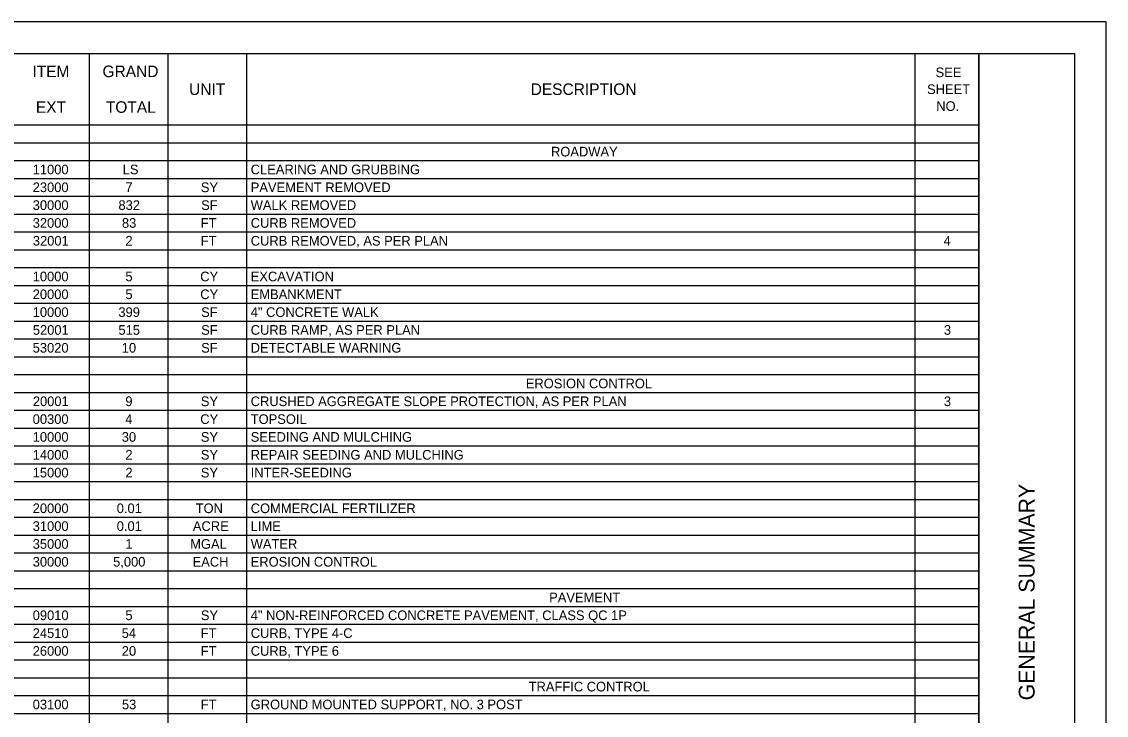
# Model space of a CAD drawing. Extents: x 0 to 34, y 0 to 22.
# Drawn here: x 16.98 to 34, y 11.11 to 22 of the extents above; entities that cross this region are included whole.
import ezdxf

# ---------------------------------------------------------------- set-up
doc = ezdxf.new("R2010")
doc.units = 0
for name, color, linetype in [('SH_Border', 7, 'Continuous'), ('SH_Cut_Line', 7, 'Continuous'), ('SH_Data', 7, 'Continuous'), ('SH_Text', 7, 'Continuous')]:
    doc.layers.add(name, color=color, linetype=linetype)

msp = doc.modelspace()

# ---------------------------------------------------------------- linework, layer by layer
at = {"layer": 'SH_Border'}
msp.add_line((32, 0.5), (32, 21.5), dxfattribs=at)
msp.add_lwpolyline([(1.5, 21.5), (33.5, 21.5), (33.5, 0.5), (1.5, 0.5)], close=True, dxfattribs=at)
at = {"layer": 'SH_Cut_Line'}
msp.add_lwpolyline([(0, 0), (34, 0), (34, 22), (0, 22)], close=True, dxfattribs=at)
at = {"layer": 'SH_Text'}
for p, q in [((1.5, 21.5), (32, 21.5)), ((18.035, 21.5), (18.035, 0.5)), ((19.27, 21.5), (19.27, 0.5)), ((20.505, 21.5), (20.505, 0.5)), ((30.995, 21.5), (30.995, 0.5)), ((32, 21.5), (32, 0.5)), ((1.5, 20.38), (32, 20.38)), ((1.5, 20.1), (32, 20.1)), ((1.5, 19.82), (32, 19.82)), ((1.5, 19.54), (32, 19.54)), ((1.5, 19.26), (32, 19.26)), ((1.5, 18.98), (32, 18.98)), ((1.5, 18.7), (32, 18.7)), ((1.5, 18.42), (32, 18.42)), ((1.5, 18.14), (32, 18.14)), ((1.5, 17.86), (32, 17.86)), ((1.5, 17.58), (32, 17.58)), ((1.5, 17.3), (32, 17.3)), ((1.5, 17.02), (32, 17.02)), ((1.5, 16.74), (32, 16.74)), ((1.5, 16.46), (32, 16.46)), ((1.5, 16.18), (32, 16.18)), ((1.5, 15.9), (32, 15.9)), ((1.5, 15.62), (32, 15.62)), ((1.5, 15.34), (32, 15.34)), ((1.5, 15.06), (32, 15.06)), ((1.5, 14.78), (32, 14.78)), ((1.5, 14.5), (32, 14.5)), ((1.5, 14.22), (32, 14.22)), ((1.5, 13.94), (32, 13.94)), ((1.5, 13.66), (32, 13.66)), ((1.5, 13.38), (32, 13.38)), ((1.5, 13.1), (32, 13.1)), ((1.5, 12.82), (32, 12.82)), ((1.5, 12.54), (32, 12.54)), ((1.5, 12.26), (32, 12.26)), ((1.5, 11.98), (32, 11.98)), ((1.5, 11.7), (32, 11.7)), ((1.5, 11.42), (32, 11.42)), ((1.5, 11.14), (32, 11.14))]:
    msp.add_line(p, q, dxfattribs=at)

# ---------------------------------------------------------------- texts
at = {"layer": 'SH_Data'}
msp.add_text('GENERAL SUMMARY', height=0.25, rotation=90, dxfattribs=at).set_placement((32.875, 11.344))
at = {"layer": 'SH_Text'}
for s, height, p in [('ITEM', 0.1818, (17.145, 21.129)), ('GRAND', 0.1818, (18.245, 21.129)), ('SEE ', 0.1515, (31.32, 21.129)), ('UNIT', 0.1818, (19.604, 20.849)), ('DESCRIPTION', 0.18184, (24.965, 20.849)), ('SHEET ', 0.1515, (31.187, 20.864)), ('EXT', 0.1818, (17.199, 20.569)), ('TOTAL', 0.1818, (18.297, 20.569)), ('NO.', 0.1515, (31.331, 20.599)), ('ROADWAY', 0.1515, (25.284, 19.884)), ('11000', 0.1515, (17.149, 19.604)), ('LS', 0.1515, (18.562, 19.604)), ('CLEARING AND GRUBBING', 0.15153, (20.571, 19.604)), ('23000', 0.1515, (17.149, 19.324)), ('7', 0.152, (18.603, 19.324)), ('SY', 0.1515, (19.788, 19.324)), ('PAVEMENT REMOVED', 0.15153, (20.571, 19.324)), ('30000', 0.1515, (17.149, 19.044)), ('832', 0.1515, (18.495, 19.044)), ('SF', 0.1515, (19.793, 19.044)), ('WALK REMOVED', 0.15153, (20.571, 19.044)), ('32000', 0.1515, (17.149, 18.764)), ('83', 0.1515, (18.55, 18.764)), ('FT', 0.1515, (19.786, 18.764)), ('CURB REMOVED', 0.15153, (20.571, 18.764)), ('32001', 0.1515, (17.151, 18.484)), ('2', 0.152, (18.604, 18.484)), ('FT', 0.1515, (19.786, 18.484)), ('CURB REMOVED, AS PER PLAN', 0.15153, (20.571, 18.484)), ('4', 0.152, (31.446, 18.484)), ('10000', 0.1515, (17.149, 17.924)), ('5', 0.152, (18.604, 17.924)), ('CY', 0.1515, (19.779, 17.924)), ('EXCAVATION', 0.1515, (20.571, 17.924)), ('20000', 0.1515, (17.149, 17.644)), ('5', 0.152, (18.604, 17.644)), ('CY', 0.1515, (19.779, 17.644)), ('EMBANKMENT', 0.1515, (20.571, 17.644)), ('10000', 0.1515, (17.149, 17.364)), ('399', 0.1515, (18.494, 17.364)), ('SF', 0.1515, (19.793, 17.364)), ('4" CONCRETE WALK', 0.15153, (20.571, 17.364)), ('52001', 0.1515, (17.151, 17.084)), ('515', 0.1515, (18.495, 17.084)), ('SF', 0.1515, (19.793, 17.084)), ('CURB RAMP, AS PER PLAN', 0.15153, (20.571, 17.084)), ('3', 0.152, (31.45, 17.084)), ('53020', 0.1515, (17.149, 16.804)), ('10', 0.1515, (18.547, 16.804)), ('SF', 0.1515, (19.793, 16.804)), ('DETECTABLE WARNING', 0.15153, (20.571, 16.804)), ('EROSION CONTROL', 0.15153, (24.889, 16.244)), ('20001', 0.1515, (17.151, 15.964)), ('9', 0.152, (18.603, 15.964)), ('SY', 0.1515, (19.788, 15.964)), ('CRUSHED AGGREGATE SLOPE PROTECTION, AS PER PLAN', 0.15153, (20.571, 15.964)), ('3', 0.152, (31.45, 15.964)), ('00300', 0.1515, (17.149, 15.684)), ('4', 0.152, (18.601, 15.684)), ('CY', 0.1515, (19.779, 15.684)), ('TOPSOIL', 0.1515, (20.571, 15.684)), ('10000', 0.1515, (17.149, 15.404)), ('30', 0.1515, (18.547, 15.404)), ('SY', 0.1515, (19.788, 15.404)), ('SEEDING AND MULCHING', 0.15153, (20.571, 15.404)), ('14000', 0.1515, (17.149, 15.124)), ('2', 0.152, (18.604, 15.124)), ('SY', 0.1515, (19.788, 15.124)), ('REPAIR SEEDING AND MULCHING', 0.15153, (20.571, 15.124)), ('15000', 0.1515, (17.149, 14.844)), ('2', 0.152, (18.604, 14.844)), ('SY', 0.1515, (19.788, 14.844)), ('INTER-SEEDING', 0.15153, (20.571, 14.844)), ('20000', 0.1515, (17.149, 14.284)), ('0.01', 0.1515, (18.468, 14.284)), ('TON', 0.1515, (19.707, 14.284)), ('COMMERCIAL FERTILIZER', 0.15153, (20.571, 14.284)), ('31000', 0.1515, (17.149, 14.004)), ('0.01', 0.1515, (18.468, 14.004)), ('ACRE', 0.1515, (19.663, 14.004)), ('LIME', 0.1515, (20.571, 14.004)), ('35000', 0.1515, (17.149, 13.724)), ('1', 0.152, (18.604, 13.724)), ('MGAL', 0.1515, (19.621, 13.724)), ('WATER', 0.1515, (20.571, 13.724)), ('30000', 0.1515, (17.149, 13.444)), ('5,000', 0.1515, (18.411, 13.444)), ('EACH', 0.1515, (19.659, 13.444)), ('EROSION CONTROL', 0.15153, (20.571, 13.444)), ('PAVEMENT', 0.1515, (25.255, 12.884)), ('09010', 0.1515, (17.149, 12.604)), ('5', 0.152, (18.604, 12.604)), ('SY', 0.1515, (19.788, 12.604)), ('4" NON-REINFORCED CONCRETE PAVEMENT, CLASS QC 1P', 0.15153, (20.571, 12.604)), ('24510', 0.1515, (17.149, 12.324)), ('54', 0.1515, (18.546, 12.324)), ('FT', 0.1515, (19.786, 12.324)), ('CURB, TYPE 4-C', 0.15153, (20.571, 12.324)), ('26000', 0.1515, (17.149, 12.044)), ('20', 0.1515, (18.547, 12.044)), ('FT', 0.1515, (19.786, 12.044)), ('CURB, TYPE 6', 0.15153, (20.571, 12.044)), ('TRAFFIC CONTROL', 0.15153, (24.933, 11.484)), ('03100', 0.1515, (17.149, 11.204)), ('53', 0.1515, (18.55, 11.204)), ('FT', 0.1515, (19.786, 11.204)), ('GROUND MOUNTED SUPPORT, NO. 3 POST', 0.15153, (20.571, 11.204))]:
    msp.add_text(s, height=height, dxfattribs=at).set_placement(p)

doc.saveas('drawing.dxf')
